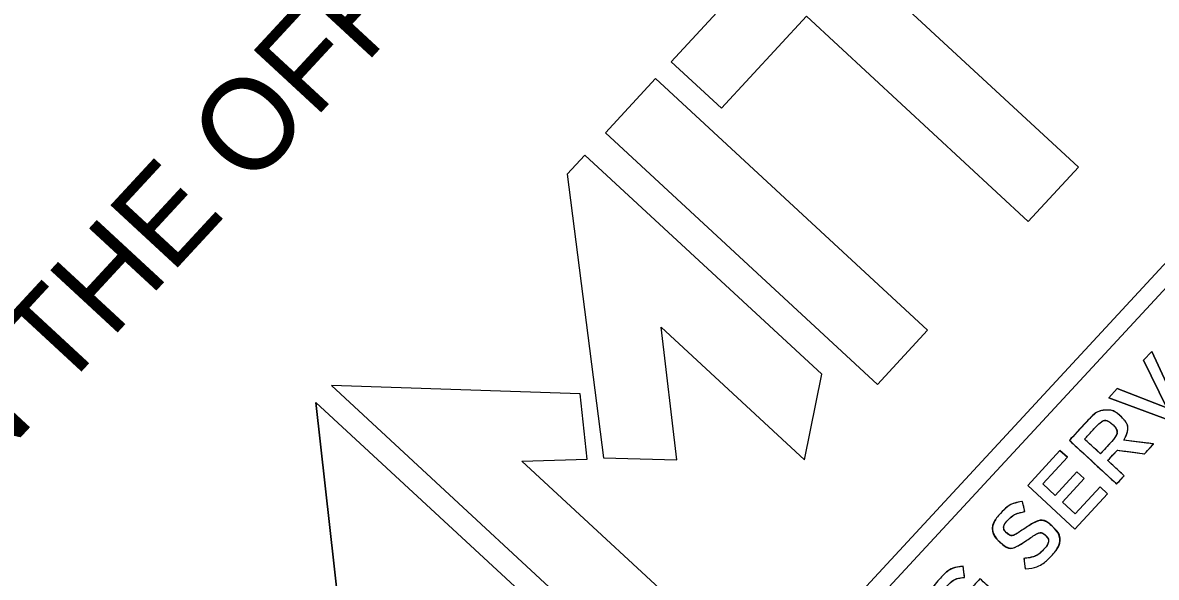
# Model space of a CAD drawing. Extents: x 1766669 to 1770980, y 998119 to 1002502.
# Drawn here: x 1769659.5 to 1769807, y 1000016.7 to 1000088.8 of the extents above; entities that cross this region are included whole.
import ezdxf

# ---------------------------------------------------------------- set-up
doc = ezdxf.new("R2010")
doc.units = 0
doc.layers.add('Default Symbol CELL', color=7, linetype='Continuous')

msp = doc.modelspace()

# ---------------------------------------------------------------- linework, layer by layer
at = {"layer": 'Default Symbol CELL'}
for p, q in [((1769802.28, 1000037.69), (1769802.26, 1000037.71)), ((1769801.31, 1000036.55), (1769801.33, 1000036.54)), ((1769789.88, 1000025.21), (1769789.6, 1000026.54)), ((1769793.48, 1000023.29), (1769793.46, 1000023.31)), ((1769786.61, 1000021.29), (1769786.63, 1000021.27)), ((1769787.53, 1000022.44), (1769787.51, 1000022.45)), ((1769792.57, 1000022.13), (1769792.59, 1000022.11)), ((1769789.77, 1000019.12), (1769789.94, 1000017.75)), ((1769782.06, 1000016.66), (1769781.87, 1000018.1))]:
    msp.add_line(p, q, dxfattribs=at)
for points in [[(1769772.03, 1000114.2), (1769778.56, 1000108.15), (1769768, 1000096.74), (1769796.86, 1000070.04), (1769790.32, 1000062.97), (1769761.46, 1000089.67), (1769750.4, 1000077.72), (1769743.87, 1000083.76), (1769772.03, 1000114.2)], [(1769743.87, 1000083.76), (1769750.4, 1000077.72), (1769761.46, 1000089.67), (1769790.32, 1000062.97), (1769796.86, 1000070.04), (1769768, 1000096.74), (1769778.56, 1000108.15), (1769772.03, 1000114.2), (1769743.87, 1000083.76)], [(1769735.32, 1000074.52), (1769741.85, 1000081.58), (1769777.24, 1000048.84), (1769770.7, 1000041.77), (1769735.32, 1000074.52)], [(1769770.7, 1000041.77), (1769777.24, 1000048.84), (1769741.85, 1000081.58), (1769735.32, 1000074.52), (1769770.7, 1000041.77)], [(1769730.33, 1000069.13), (1769735.07, 1000032.2), (1769744.63, 1000031.95), (1769742.57, 1000049.21), (1769761.23, 1000031.94), (1769763.49, 1000043.08), (1769732.64, 1000071.62), (1769730.33, 1000069.13)], [(1769730.33, 1000069.13), (1769735.07, 1000032.2), (1769744.63, 1000031.95), (1769742.57, 1000049.21), (1769761.23, 1000031.94), (1769763.49, 1000043.08), (1769732.64, 1000071.62), (1769730.33, 1000069.13)], [(1769821.38, 1000068.54), (1769662.96, 999897.34), (1769661.33, 999898.85), (1769819.74, 1000070.05), (1769821.38, 1000068.54)], [(1769819.74, 1000070.05), (1769661.33, 999898.85), (1769662.96, 999897.34), (1769821.38, 1000068.54), (1769819.74, 1000070.05)], [(1769800.81, 1000040.03), (1769801.92, 1000041.22), (1769808.35, 1000038.7), (1769805.33, 1000044.91), (1769806.41, 1000046.07), (1769810.24, 1000037.81), (1769809.36, 1000036.86), (1769800.81, 1000040.03)], [(1769809.36, 1000036.86), (1769810.24, 1000037.81), (1769806.41, 1000046.07), (1769805.33, 1000044.91), (1769808.35, 1000038.7), (1769801.92, 1000041.22), (1769800.81, 1000040.03), (1769809.36, 1000036.86)], [(1769699.66, 1000041.61), (1769742.75, 1000001.73), (1769749.29, 1000008.8), (1769724.43, 1000031.8), (1769732.93, 1000032.06), (1769732.02, 1000040.54), (1769699.66, 1000041.61)], [(1769699.66, 1000041.61), (1769742.75, 1000001.73), (1769749.29, 1000008.8), (1769724.43, 1000031.8), (1769732.93, 1000032.06), (1769732.02, 1000040.54), (1769699.66, 1000041.61)], [(1769697.65, 1000039.43), (1769740.74, 999999.56), (1769734.2, 999992.5), (1769709.35, 1000015.49), (1769709.75, 1000007), (1769701.22, 1000007.26), (1769697.65, 1000039.43)], [(1769701.22, 1000007.26), (1769709.75, 1000007), (1769709.35, 1000015.49), (1769734.2, 999992.5), (1769740.74, 999999.56), (1769697.65, 1000039.43), (1769701.22, 1000007.26)], [(1769798.21, 1000037.22), (1769795.69, 1000034.49), (1769801.83, 1000028.81), (1769802.82, 1000029.88), (1769800.68, 1000031.87), (1769801.93, 1000033.21), (1769805.46, 1000032.74), (1769806.65, 1000034.02), (1769802.79, 1000034.51)], [(1769801.19, 1000034.33), (1769799.73, 1000032.75), (1769797.66, 1000034.66), (1769799.12, 1000036.23)], [(1769790.26, 1000028.62), (1769794.46, 1000033.17), (1769795.43, 1000032.28), (1769792.22, 1000028.81), (1769793.82, 1000027.33), (1769796.66, 1000030.4), (1769797.63, 1000029.51), (1769794.78, 1000026.44), (1769796.43, 1000024.91), (1769799.68, 1000028.42), (1769800.64, 1000027.53), (1769796.4, 1000022.94), (1769790.26, 1000028.62)], [(1769796.4, 1000022.94), (1769800.64, 1000027.53), (1769799.68, 1000028.42), (1769796.43, 1000024.91), (1769794.78, 1000026.44), (1769797.63, 1000029.51), (1769796.66, 1000030.4), (1769793.82, 1000027.33), (1769792.22, 1000028.81), (1769795.43, 1000032.28), (1769794.46, 1000033.17), (1769790.26, 1000028.62), (1769796.4, 1000022.94)]]:
    msp.add_lwpolyline(points, dxfattribs=at)
for points, degree in [([(1769795.69, 1000034.49), (1769795.69, 1000034.49), (1769798.21, 1000037.22), (1769798.21, 1000037.22), (1769798.93, 1000037.99), (1769799.71, 1000038.39), (1769800.46, 1000038.42), (1769801.1, 1000038.44), (1769801.72, 1000038.2), (1769802.26, 1000037.71), (1769802.26, 1000037.71), (1769802.28, 1000037.69), (1769802.28, 1000037.69), (1769803.29, 1000036.76), (1769803.33, 1000035.59), (1769802.79, 1000034.51), (1769802.79, 1000034.51), (1769806.65, 1000034.02), (1769806.65, 1000034.02), (1769806.65, 1000034.02), (1769805.46, 1000032.74), (1769805.46, 1000032.74), (1769805.46, 1000032.74), (1769801.93, 1000033.21), (1769801.93, 1000033.21), (1769801.93, 1000033.21), (1769800.68, 1000031.87), (1769800.68, 1000031.87), (1769800.68, 1000031.87), (1769802.82, 1000029.88), (1769802.82, 1000029.88), (1769802.82, 1000029.88), (1769801.83, 1000028.81), (1769801.83, 1000028.81), (1769801.83, 1000028.81), (1769795.69, 1000034.49), (1769795.69, 1000034.49)], 3), ([(1769802.26, 1000037.71), (1769801.72, 1000038.2), (1769801.1, 1000038.44), (1769800.46, 1000038.42), (1769799.71, 1000038.39), (1769798.93, 1000037.99), (1769798.21, 1000037.22)], 3), ([(1769802.79, 1000034.51), (1769803.33, 1000035.59), (1769803.29, 1000036.76), (1769802.28, 1000037.69)], 2), ([(1769801.19, 1000034.33), (1769801.9, 1000035.1), (1769801.95, 1000035.96), (1769801.33, 1000036.54), (1769801.33, 1000036.54), (1769801.31, 1000036.55), (1769801.31, 1000036.55), (1769800.65, 1000037.16), (1769799.85, 1000037.02), (1769799.12, 1000036.23), (1769799.12, 1000036.23), (1769797.66, 1000034.66), (1769797.66, 1000034.66), (1769797.66, 1000034.66), (1769799.73, 1000032.75), (1769799.73, 1000032.75), (1769799.73, 1000032.75), (1769801.19, 1000034.33), (1769801.19, 1000034.33)], 3), ([(1769799.12, 1000036.23), (1769799.85, 1000037.02), (1769800.65, 1000037.16), (1769801.31, 1000036.55)], 2), ([(1769801.33, 1000036.54), (1769801.95, 1000035.96), (1769801.9, 1000035.1), (1769801.19, 1000034.33)], 2), ([(1769789.6, 1000026.54), (1769788.52, 1000026.38), (1769787.59, 1000025.92), (1769786.77, 1000025.03), (1769785.64, 1000023.81), (1769785.56, 1000022.26), (1769786.61, 1000021.29)], 3), ([(1769789.94, 1000017.75), (1769789.94, 1000017.75), (1769789.77, 1000019.12), (1769789.77, 1000019.12), (1769790.82, 1000019.23), (1769791.66, 1000019.56), (1769792.35, 1000020.31), (1769792.97, 1000020.98), (1769793.04, 1000021.69), (1769792.59, 1000022.11), (1769792.59, 1000022.11), (1769792.57, 1000022.13), (1769792.57, 1000022.13), (1769792.13, 1000022.54), (1769791.67, 1000022.51), (1769790.35, 1000021.62), (1769788.83, 1000020.6), (1769787.76, 1000020.22), (1769786.63, 1000021.27), (1769786.63, 1000021.27), (1769786.61, 1000021.29), (1769786.61, 1000021.29), (1769785.56, 1000022.26), (1769785.64, 1000023.81), (1769786.77, 1000025.03), (1769787.59, 1000025.92), (1769788.52, 1000026.38), (1769789.6, 1000026.54), (1769789.6, 1000026.54), (1769789.88, 1000025.21), (1769789.88, 1000025.21), (1769788.96, 1000025.04), (1769788.23, 1000024.69), (1769787.71, 1000024.13), (1769787.12, 1000023.5), (1769787.11, 1000022.83), (1769787.51, 1000022.45), (1769787.51, 1000022.45), (1769787.53, 1000022.44), (1769787.53, 1000022.44), (1769788, 1000022), (1769788.47, 1000022.09), (1769789.85, 1000023.01), (1769791.36, 1000024.01), (1769792.44, 1000024.25), (1769793.46, 1000023.31), (1769793.46, 1000023.31), (1769793.48, 1000023.29), (1769793.48, 1000023.29), (1769794.63, 1000022.23), (1769794.48, 1000020.69), (1769793.29, 1000019.4), (1769792.42, 1000018.47), (1769791.28, 1000017.88), (1769789.94, 1000017.75)], 3), ([(1769787.51, 1000022.45), (1769787.11, 1000022.83), (1769787.12, 1000023.5), (1769787.71, 1000024.13), (1769788.23, 1000024.69), (1769788.96, 1000025.04), (1769789.88, 1000025.21)], 3), ([(1769793.46, 1000023.31), (1769792.44, 1000024.25), (1769791.36, 1000024.01), (1769789.85, 1000023.01), (1769788.47, 1000022.09), (1769788, 1000022), (1769787.53, 1000022.44)], 3), ([(1769789.94, 1000017.75), (1769791.28, 1000017.88), (1769792.42, 1000018.47), (1769793.29, 1000019.4), (1769794.48, 1000020.69), (1769794.63, 1000022.23), (1769793.48, 1000023.29)], 3), ([(1769786.63, 1000021.27), (1769787.76, 1000020.22), (1769788.83, 1000020.6), (1769790.35, 1000021.62), (1769791.67, 1000022.51), (1769792.13, 1000022.54), (1769792.57, 1000022.13)], 3), ([(1769792.59, 1000022.11), (1769793.04, 1000021.69), (1769792.97, 1000020.98), (1769792.35, 1000020.31), (1769791.66, 1000019.56), (1769790.82, 1000019.23), (1769789.77, 1000019.12)], 3), ([(1769779.13, 1000010.4), (1769779.13, 1000010.4), (1769779.11, 1000010.42), (1769779.11, 1000010.42), (1769777.39, 1000012.01), (1769777.15, 1000014.67), (1769778.86, 1000016.52), (1769779.85, 1000017.59), (1769780.75, 1000017.97), (1769781.87, 1000018.1), (1769781.87, 1000018.1), (1769782.06, 1000016.66), (1769782.06, 1000016.66), (1769781.22, 1000016.56), (1769780.53, 1000016.34), (1769779.81, 1000015.56), (1769778.76, 1000014.43), (1769778.96, 1000012.65), (1769780.14, 1000011.56), (1769780.14, 1000011.56), (1769780.16, 1000011.55), (1769780.16, 1000011.55), (1769781.42, 1000010.38), (1769783.12, 1000010.35), (1769784.28, 1000011.6), (1769784.81, 1000012.18), (1769785.11, 1000012.88), (1769785.18, 1000013.51), (1769785.18, 1000013.51), (1769784.03, 1000014.58), (1769784.03, 1000014.58), (1769784.03, 1000014.58), (1769782.58, 1000013.01), (1769782.58, 1000013.01), (1769782.58, 1000013.01), (1769781.64, 1000013.88), (1769781.64, 1000013.88), (1769781.64, 1000013.88), (1769784.06, 1000016.49), (1769784.06, 1000016.49), (1769784.06, 1000016.49), (1769786.64, 1000014.1), (1769786.64, 1000014.1), (1769786.6, 1000013.02), (1769786.23, 1000011.74), (1769785.23, 1000010.66), (1769783.45, 1000008.74), (1769780.92, 1000008.75), (1769779.13, 1000010.4)], 3), ([(1769781.87, 1000018.1), (1769780.75, 1000017.97), (1769779.85, 1000017.59), (1769778.86, 1000016.52), (1769777.15, 1000014.67), (1769777.39, 1000012.01), (1769779.11, 1000010.42)], 3), ([(1769780.14, 1000011.56), (1769778.96, 1000012.65), (1769778.76, 1000014.43), (1769779.81, 1000015.56), (1769780.53, 1000016.34), (1769781.22, 1000016.56), (1769782.06, 1000016.66)], 3)]:
    msp.add_open_spline(points, degree=degree, dxfattribs=at)

# ---------------------------------------------------------------- texts
msp.add_text('PREPARED IN THE OFFICE OF', height=11.9316, rotation=47.237, dxfattribs=at).set_placement((1769587.89, 999957.74))

doc.saveas('drawing.dxf')
